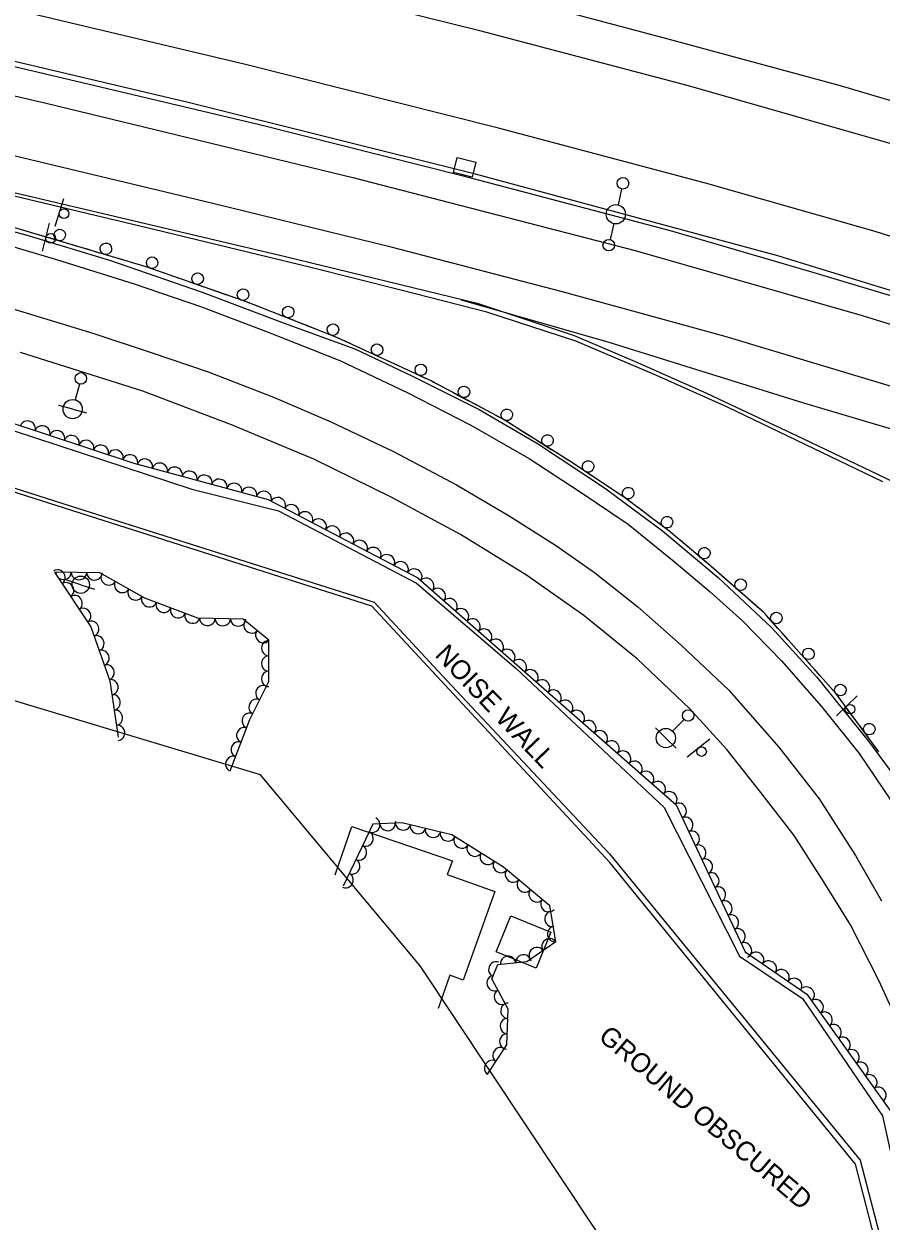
# Model space of a CAD drawing. Extents: x 1722896 to 1754269, y 648279 to 666297.
# Drawn here: x 1729933.1 to 1730155.7, y 652271.6 to 652582.6 of the extents above; entities that cross this region are included whole.
import ezdxf

# ---------------------------------------------------------------- set-up
doc = ezdxf.new("R2010")
doc.units = 0
for name, color, linetype in [('DESIGN - CENTERLINE - Proposed Text', 7, 'Continuous'), ('DESIGN - PUBLIC HEARING - Shapes', 7, 'Continuous'), ('DESIGN - SCRATCH - User 1', 7, 'Continuous'), ('SURVEY - CENTERLINE - Preliminary', 7, 'Continuous'), ('SURVEY - CENTERLINE - Preliminary Text', 7, 'Continuous'), ('SURVEY - DRAINAGE - Natural Features', 7, 'Continuous'), ('SURVEY - DTM - Breaklines', 7, 'Continuous'), ('SURVEY - VEGETATION - Features with Text', 7, 'Continuous')]:
    doc.layers.add(name, color=color, linetype=linetype)

msp = doc.modelspace()

# ---------------------------------------------------------------- linework, layer by layer
at = {"layer": 'DESIGN - CENTERLINE - Proposed Text'}
msp.add_lwpolyline([(1730013.96, 652361.53), (1730018.28, 652374.1), (1730044.37, 652365.21), (1730043.02, 652361.67), (1730055.41, 652357.27), (1730047.19, 652334.16), (1730043.67, 652335.5), (1730040.65, 652326.82)], dxfattribs=at)
msp.add_lwpolyline([(1730059.51, 652350.89), (1730069.89, 652346.65), (1730066.09, 652337.35), (1730055.71, 652341.59)], close=True, dxfattribs=at)
at = {"layer": 'DESIGN - PUBLIC HEARING - Shapes'}
for p, q in [((1729941.21, 652530.08), (1729943.48, 652537.22)), ((1729937.92, 652523.53), (1729939.79, 652530.79)), ((1730144.07, 652402.83), (1730149.42, 652408.08)), ((1730105.36, 652392.17), (1730111.19, 652396.88))]:
    msp.add_line(p, q, dxfattribs=at)
for centre in [(1729943.52, 652533.3), (1729940.05, 652526.88), (1730147.62, 652404.59), (1730109.06, 652393.58)]:
    msp.add_circle(centre, 1.25, dxfattribs=at)
at = {"layer": 'DESIGN - SCRATCH - User 1'}
for points in [[(1730260.5, 652481.12), (1730200.23, 652500.38), (1730128.84, 652522.38), (1730050.34, 652543.58), (1729975.77, 652562.21), (1729903.48, 652579.22), (1729810.16, 652600.96), (1729713.26, 652623.18), (1729589.34, 652652.13), (1729504.2, 652671.83), (1729418.48, 652691.69), (1729323.79, 652714.91), (1729300.24, 652718.9), (1729241.89, 652732.44), (1729159, 652752.12), (1729085.49, 652769.36), (1729012.25, 652788.71), (1728967.13, 652802.09)], [(1729322.32, 652714.08), (1729353.29, 652706.05), (1729426.46, 652688.63), (1729487, 652674.52), (1729543.44, 652661.54), (1729603.31, 652647.77), (1729684.6, 652628.54), (1729746.94, 652614.26), (1729794.94, 652603.07), (1729852.02, 652590.16), (1729894.66, 652579.99), (1729944.99, 652568.14), (1729994.29, 652556.46), (1730046.83, 652543.24), (1730100.94, 652528.96), (1730138.19, 652518.06), (1730180.91, 652505.22), (1730226.29, 652490.48), (1730260.14, 652479.46), (1730260.49, 652479.32)], [(1730155.11, 652393.52), (1730144.08, 652408.45), (1730135.73, 652417.94), (1730125.19, 652429.69), (1730110.77, 652442.32), (1730100.58, 652450.92), (1730089.44, 652459.3), (1730075.54, 652468.54), (1730057.34, 652480.01), (1730038.85, 652489.84), (1730014.4, 652501.15), (1729990.88, 652510.38), (1729964.82, 652519.52), (1729928.18, 652530.42), (1729886.57, 652541.81), (1729844.85, 652552.44), (1729803.55, 652565.53), (1729787.6, 652570.85)], [(1730156.12, 652463.67), (1730115.8, 652483.07), (1730097.15, 652491.31), (1730076.44, 652500.16), (1730053.34, 652507.68), (1730031.02, 652513.43), (1730007.63, 652519.31), (1729966.83, 652529.17), (1729878.66, 652550.21), (1729811, 652566.11), (1729790.9, 652570.56), (1729791.32, 652572.2), (1729835.78, 652561.08), (1729891.23, 652548.04), (1729941.54, 652536.16), (1730001.06, 652522.18), (1730050.79, 652510.07), (1730075.99, 652501.68), (1730092.46, 652494.61), (1730110.48, 652486.56), (1730135.33, 652474.9), (1730169.02, 652458.81)], [(1729710.95, 652524.89), (1729776.44, 652507.44), (1729862.1, 652483.88), (1729945.16, 652457.43), (1730024.08, 652432.36), (1730042.84, 652412.15), (1730085.15, 652367.01), (1730150.27, 652287.4), (1730165.53, 652228.54), (1730168.51, 652212.11), (1730166.64, 652211.96), (1730163.75, 652229.34), (1730149.01, 652286.42), (1730085.22, 652364.8), (1730023.49, 652431.35), (1729919.69, 652464.42), (1729854.38, 652484.95), (1729763.84, 652509.44), (1729638.78, 652542.79)], [(1729935.97, 652528.1), (1729933.71, 652528.77)], [(1729938.22, 652527.43), (1729935.97, 652528.1)], [(1729944.16, 652525.66), (1729939.75, 652526.98)], [(1729947.95, 652524.54), (1729945.7, 652525.21)], [(1729950.2, 652523.87), (1729947.95, 652524.54)], [(1729956.14, 652522.1), (1729951.73, 652523.41)], [(1729959.93, 652520.97), (1729957.68, 652521.65)], [(1729962.18, 652520.31), (1729959.93, 652520.97)], [(1729968.07, 652518.38), (1729964.82, 652519.52), (1729963.72, 652519.85)], [(1729971.8, 652517.07), (1729969.58, 652517.85)], [(1729974.02, 652516.29), (1729971.8, 652517.07)], [(1729979.87, 652514.24), (1729975.53, 652515.76)], [(1729983.6, 652512.93), (1729981.38, 652513.71)], [(1729985.81, 652512.16), (1729983.6, 652512.93)], [(1729991.65, 652510.08), (1729990.88, 652510.38), (1729987.32, 652511.63)], [(1729995.33, 652508.63), (1729993.14, 652509.49)], [(1729997.52, 652507.77), (1729995.33, 652508.63)], [(1730003.29, 652505.51), (1729999.01, 652507.19)], [(1730006.97, 652504.07), (1730004.78, 652504.92)], [(1730009.15, 652503.21), (1730006.97, 652504.07)], [(1730014.91, 652500.91), (1730014.4, 652501.15), (1730010.64, 652502.62)], [(1730018.5, 652499.25), (1730016.36, 652500.24)], [(1730020.63, 652498.27), (1730018.5, 652499.25)], [(1730026.26, 652495.66), (1730022.08, 652497.59)], [(1730029.84, 652494.01), (1730027.71, 652494.99)], [(1730031.98, 652493.02), (1730029.84, 652494.01)], [(1730037.6, 652490.42), (1730033.43, 652492.35)], [(1730041.12, 652488.63), (1730039.05, 652489.73)], [(1730043.2, 652487.53), (1730041.12, 652488.63)], [(1730048.67, 652484.62), (1730044.61, 652486.78)], [(1730052.16, 652482.76), (1730050.09, 652483.86)], [(1730054.24, 652481.66), (1730052.16, 652482.76)], [(1730059.61, 652478.58), (1730057.34, 652480.01), (1730055.65, 652480.91)], [(1730062.95, 652476.47), (1730060.96, 652477.72)], [(1730064.94, 652475.22), (1730062.95, 652476.47)], [(1730070.19, 652471.91), (1730066.29, 652474.36)], [(1730073.53, 652469.81), (1730071.54, 652471.06)], [(1730075.52, 652468.55), (1730073.53, 652469.81)], [(1730080.68, 652465.12), (1730076.85, 652467.67)], [(1730083.97, 652462.93), (1730082.01, 652464.23)], [(1730085.93, 652461.63), (1730083.97, 652462.93)], [(1730091.02, 652458.1), (1730089.44, 652459.3), (1730087.26, 652460.75)], [(1730094.18, 652455.73), (1730092.3, 652457.14)], [(1730096.06, 652454.32), (1730094.18, 652455.73)], [(1730100.99, 652450.57), (1730100.58, 652450.92), (1730097.33, 652453.36)], [(1730104.01, 652448.02), (1730102.21, 652449.54)], [(1730105.81, 652446.5), (1730104.01, 652448.02)], [(1730110.54, 652442.51), (1730107.03, 652445.47)], [(1730113.52, 652439.91), (1730111.75, 652441.45)], [(1730115.29, 652438.36), (1730113.52, 652439.91)], [(1730119.96, 652434.28), (1730116.49, 652437.31)], [(1730122.93, 652431.68), (1730121.16, 652433.22)], [(1730124.7, 652430.13), (1730122.93, 652431.68)], [(1730128.89, 652425.57), (1730125.82, 652428.99)], [(1730131.53, 652422.63), (1730129.96, 652424.38)], [(1730133.09, 652420.88), (1730131.53, 652422.63)], [(1730137.22, 652416.24), (1730135.73, 652417.94), (1730134.16, 652419.68)], [(1730139.82, 652413.28), (1730138.27, 652415.04)], [(1730141.38, 652411.52), (1730139.82, 652413.28)], [(1730145.33, 652406.75), (1730144.08, 652408.45), (1730142.43, 652410.31)], [(1730147.68, 652403.57), (1730146.29, 652405.46)], [(1730149.08, 652401.68), (1730147.68, 652403.57)], [(1730152.77, 652396.7), (1730150.03, 652400.4)], [(1730155.11, 652393.52), (1730153.72, 652395.41)]]:
    msp.add_lwpolyline(points, dxfattribs=at)
for centre, start, end in [((1729942.41, 652527.75), 6.6967, 6.6869), ((1729954.39, 652524.19), 6.6967, 6.6869), ((1729966.42, 652520.55), 3.9321, 3.9223), ((1729978.22, 652516.41), 3.9321, 3.9223), ((1729990.01, 652512.27), 3.9321, 3.9223), ((1730001.72, 652507.74), 1.829, 1.8192), ((1730013.35, 652503.17), 1.829, 1.8192), ((1730024.82, 652497.98), 358.4422, 358.4324), ((1730036.16, 652492.73), 358.4422, 358.4324), ((1730047.37, 652487.01), 355.2567, 355.2468), ((1730058.48, 652481.06), 351.0441, 351.0343), ((1730069.06, 652474.4), 351.0441, 351.0343), ((1730079.61, 652467.63), 349.6354, 349.6256), ((1730090.02, 652460.71), 349.6354, 349.6256), ((1730100.09, 652453.16), 346.307, 346.2972), ((1730109.77, 652445.12), 343.0958, 343.086), ((1730119.23, 652436.91), 342.0779, 342.0681), ((1730128.49, 652428.27), 335.1128, 335.103), ((1730136.83, 652418.95), 335.1128, 335.103), ((1730145.09, 652409.56), 334.6142, 334.6044), ((1730152.62, 652399.42), 329.7361, 329.7263)]:
    msp.add_arc(centre, 1.5, start, end, dxfattribs=at)
at = {"layer": 'SURVEY - CENTERLINE - Preliminary'}
for points in [[(1729712.09, 652539.06), (1729728.16, 652532.32), (1729731.95, 652531.44), (1729747.26, 652527.61), (1729783.86, 652517.45), (1729852.77, 652501.75), (1729907.09, 652484.58), (1729976.73, 652461.75), (1729999.25, 652456.08), (1730035.09, 652437.32), (1730060.96, 652415.12), (1730099.34, 652379.07), (1730118.88, 652340.44), (1730135.26, 652329.44), (1730156.05, 652298.94), (1730163.28, 652265.89), (1730169.18, 652222.37), (1730169.88, 652205.25), (1730158.68, 652204.09), (1730146.64, 652237.53), (1730139.98, 652255.94), (1730101.32, 652254.25), (1730090.54, 652255.85)], [(1730090.54, 652255.85), (1730036, 652337.91), (1729994.57, 652387.51), (1729869.07, 652425.27), (1729760.53, 652456.24), (1729772.95, 652462.64), (1729809.33, 652453.29), (1729823.84, 652469.84), (1729849.89, 652467.63), (1729857.75, 652476.95), (1729812.74, 652489.8), (1729795.66, 652480.5), (1729760.73, 652486.71), (1729733.92, 652471.18), (1729724.15, 652467.9), (1729664.75, 652484.03)]]:
    msp.add_lwpolyline(points, dxfattribs=at)
at = {"layer": 'SURVEY - CENTERLINE - Preliminary Text'}
for points in [[(1730270.3, 652515.2), (1730228.96, 652529.12), (1730166.13, 652549.21), (1730105.7, 652566.49), (1730051.45, 652580.8), (1730001.69, 652593.2), (1729955.68, 652604.21), (1729906, 652615.94), (1729848.69, 652629.12), (1729783.93, 652644.03), (1729726.92, 652657.34), (1729658.34, 652673.01), (1729604.33, 652685.78), (1729534.44, 652701.71), (1729459.5, 652718.9), (1729384.48, 652736.76), (1729323.16, 652750.51), (1729258.16, 652765.72), (1729169.76, 652786), (1729121.61, 652797.37), (1729018.16, 652823.93), (1728918.71, 652854.37)], [(1730264.12, 652492.62), (1730202.7, 652513.21), (1730154.17, 652528.69), (1730110.08, 652541.21), (1730056.32, 652555.48), (1729990.67, 652572.07), (1729928.6, 652586.81), (1729860.63, 652602.43), (1729797.44, 652617.47), (1729715.52, 652636.12), (1729640.3, 652653.56), (1729569.25, 652670.14), (1729500.79, 652685.57), (1729431.64, 652701.97), (1729354.64, 652719.58), (1729285.63, 652735.52), (1729212.27, 652752.8), (1729127.4, 652772.45), (1729037.59, 652794.76), (1728950.93, 652819.74), (1728930.15, 652826.14)], [(1728923.18, 652804.43), (1728976.92, 652786.42), (1729028.71, 652771.38), (1729089.83, 652756), (1729155.11, 652740.87), (1729217.1, 652726.75), (1729283.33, 652711.33), (1729334.81, 652699.48), (1729422.85, 652679.58), (1729666.73, 652624.57), (1729724.92, 652611.43), (1729788.41, 652596.68), (1729859.59, 652580.32), (1729938.86, 652561.99), (1730018.53, 652542.72), (1730091.86, 652523.7), (1730150.75, 652506.89), (1730199.99, 652491.57), (1730225.61, 652483.06), (1730258.51, 652471.91)], [(1729313.44, 652763.39), (1729359.16, 652752.98), (1729405.2, 652742.92), (1729445.49, 652732.9), (1729483.13, 652724.56), (1729529.93, 652713.81), (1729584.3, 652701.06), (1729638.29, 652688.6), (1729679.44, 652678.98), (1729738.84, 652665.33), (1729794.39, 652652.3), (1729839.68, 652641.7), (1729884.25, 652631.88), (1729931.01, 652620.85), (1729974.63, 652610.32), (1730017.13, 652600.05), (1730062.15, 652588.94), (1730099.35, 652579), (1730145.03, 652566.56), (1730174.24, 652557.91), (1730207.51, 652547.77), (1730238.01, 652536.75), (1730272.76, 652524.88)], [(1730254.53, 652456.82), (1730250.06, 652458.51), (1730204.24, 652474.26), (1730164.72, 652486.48), (1730115.23, 652501.41), (1730072.65, 652513.09), (1730028.51, 652524.57), (1729982.18, 652535.95), (1729930.49, 652548.32), (1729876.45, 652560.54), (1729824.27, 652572.87), (1729762.63, 652586.89), (1729723.44, 652596.01)], [(1729719.86, 652579.69), (1729751.72, 652571.47), (1729784.3, 652563.22), (1729813.6, 652555.7), (1729841.56, 652548.32), (1729881.54, 652537.96), (1729920.24, 652527.74), (1729941.62, 652521.43), (1729961.73, 652515.05), (1729979.23, 652509.1), (1729996.52, 652502.56), (1730015.18, 652495.12), (1730032.84, 652486.79), (1730049.02, 652478.46), (1730064.28, 652469.66), (1730077.57, 652461.05), (1730090, 652452.61), (1730101.97, 652442.99), (1730111.3, 652435.11), (1730119.8, 652427.47), (1730129.82, 652417.18), (1730140.2, 652405.31), (1730149.97, 652393.07), (1730158.31, 652380.8)], [(1729790.8, 652572.08), (1729745.5, 652582.35), (1729744.78, 652578.02), (1729774.09, 652570.27), (1729806.92, 652561.19), (1729849.03, 652550.26), (1729901.03, 652536.52), (1729933.66, 652527.76), (1729955.3, 652521.19), (1729979.44, 652512.95), (1730000.65, 652504.83), (1730019.07, 652498.16), (1730034.01, 652491.12), (1730051.28, 652482.46), (1730066.45, 652473.59), (1730083.89, 652462.04), (1730098.93, 652450.95), (1730113.36, 652438.8), (1730127.25, 652425.77), (1730138.99, 652412.87), (1730152.63, 652395.91), (1730159.01, 652387.36)], [(1729663.92, 652578.37), (1729721.29, 652563.73), (1729773.42, 652550.21), (1729822.73, 652537.33), (1729880.29, 652522.14), (1729903.71, 652516.01), (1729930.83, 652508.44), (1729951.3, 652502.14), (1729966.17, 652497.23), (1729980.97, 652492.21), (1729997.88, 652485.6), (1730012.67, 652479.35), (1730029.07, 652471.55), (1730045.47, 652462.87), (1730059.15, 652454.78), (1730071.4, 652447.05), (1730081.28, 652440.12), (1730092.53, 652431.14), (1730103.75, 652421.21), (1730116.11, 652409.51), (1730129.11, 652394.72), (1730139.57, 652381.29), (1730149.03, 652366.61), (1730155.81, 652354.76)], [(1730251.24, 652447.34), (1730215, 652459.46), (1730178.82, 652471.25), (1730135.6, 652484.11), (1730085.03, 652499.86), (1730046.74, 652510.81)], [(1730162.43, 652318.02), (1730155.2, 652333.94), (1730147.74, 652348.57), (1730140.87, 652359.55), (1730133.1, 652371.81), (1730124.49, 652382.96), (1730115.58, 652394.07), (1730105.96, 652404.79), (1730092.36, 652417.65), (1730078.49, 652428.93), (1730063.62, 652439.37), (1730046.5, 652449.97), (1730028.67, 652459.6), (1730008.37, 652469.5), (1729986.98, 652478.49), (1729964, 652487.19), (1729932.27, 652497.22)]]:
    msp.add_lwpolyline(points, dxfattribs=at)
at = {"layer": 'SURVEY - DRAINAGE - Natural Features'}
msp.add_line((1730047.55, 652545.32), (1730047.55, 652545.32), dxfattribs=at)
msp.add_lwpolyline([(1730044.64, 652543.99), (1730045.62, 652547.87), (1730050.47, 652546.64), (1730049.48, 652542.76), (1730044.64, 652543.99)], dxfattribs=at)
at = {"layer": 'SURVEY - DTM - Breaklines'}
for p, q in [((1730088.31, 652539.73), (1730087.37, 652535.59)), ((1730086.25, 652530.71), (1730085.3, 652526.57)), ((1729947.53, 652489.05), (1729946.43, 652484.94)), ((1729945.78, 652482.53), (1729942.16, 652483.5)), ((1729945.78, 652482.53), (1729949.41, 652481.56)), ((1729947.87, 652436.92), (1729944.3, 652438.07)), ((1729947.87, 652436.92), (1729951.44, 652435.76)), ((1730099.78, 652397.08), (1730097.11, 652399.73)), ((1730104.53, 652401.87), (1730101.54, 652398.86)), ((1730099.78, 652397.08), (1730102.44, 652394.44))]:
    msp.add_line(p, q, dxfattribs=at)
for centre, radius in [((1730088.65, 652541.19), 1.5), ((1730086.81, 652533.15), 2.5), ((1730084.97, 652525.11), 1.5), ((1729947.91, 652490.5), 1.5), ((1729945.78, 652482.53), 2.5), ((1729947.87, 652436.92), 2.25), ((1730105.59, 652402.94), 1.5), ((1730099.78, 652397.08), 2.5)]:
    msp.add_circle(centre, radius, dxfattribs=at)
at = {"layer": 'SURVEY - VEGETATION - Features with Text'}
for points in [[(1729714.11, 652540.99), (1729737.14, 652533.33), (1729764.39, 652524.93), (1729818.06, 652511.42), (1729854.61, 652503.23), (1729904.79, 652487.26), (1729961.66, 652468.47), (1729996.53, 652459.02), (1730035.41, 652438.67), (1730102.51, 652379.73), (1730120.4, 652341.52), (1730136.4, 652330.56), (1730158.18, 652300.06), (1730169.43, 652249.19), (1730170.91, 652201.84), (1730165.15, 652167.2), (1730168.44, 652157.78), (1730155.04, 652104.77), (1730135.05, 652092.16), (1730123.31, 652106.61), (1730092.69, 652120.33)], [(1729986.66, 652388.53), (1729991.79, 652401.92), (1729996.68, 652411.75), (1729996.73, 652422.47), (1729990.03, 652428.01), (1729978.28, 652428.23), (1729964.52, 652433.45), (1729952.8, 652440), (1729941.04, 652440.18), (1729950.52, 652425.99), (1729955.44, 652411.98), (1729957.59, 652397.33)], [(1730053.52, 652309.74), (1730058.49, 652317.36), (1730058.81, 652326.65), (1730054.63, 652334.51), (1730056.19, 652338.26), (1730063.73, 652339.03), (1730071.24, 652344.28), (1730069.66, 652353.49), (1730057.61, 652363.56), (1730044.26, 652371.93), (1730031.22, 652375.1), (1730023.72, 652374.68), (1730015.99, 652358.57)]]:
    msp.add_lwpolyline(points, dxfattribs=at)
for centre, major_axis in [((1729934.12, 652477.57), (1.9, -0.63)), ((1729937.92, 652476.32), (1.9, -0.63)), ((1729941.72, 652475.06), (1.9, -0.63)), ((1729945.52, 652473.81), (1.9, -0.63)), ((1729949.31, 652472.55), (1.9, -0.63)), ((1729953.11, 652471.3), (1.9, -0.63)), ((1729956.91, 652470.04), (1.9, -0.63)), ((1729960.71, 652468.79), (1.9, -0.63)), ((1729964.55, 652467.69), (1.93, -0.52)), ((1729968.41, 652466.64), (1.93, -0.52)), ((1729972.27, 652465.6), (1.93, -0.52)), ((1729976.14, 652464.55), (1.93, -0.52)), ((1729980, 652463.51), (1.93, -0.52)), ((1729983.86, 652462.46), (1.93, -0.52)), ((1729987.72, 652461.41), (1.93, -0.52)), ((1729991.58, 652460.37), (1.93, -0.52)), ((1729995.44, 652459.32), (1.93, -0.52)), ((1729999.07, 652457.69), (1.77, -0.93)), ((1730002.62, 652455.84), (1.77, -0.93)), ((1730006.16, 652453.98), (1.77, -0.93)), ((1730009.7, 652452.13), (1.77, -0.93)), ((1730013.25, 652450.27), (1.77, -0.93)), ((1730016.79, 652448.42), (1.77, -0.93)), ((1730020.33, 652446.56), (1.77, -0.93)), ((1730023.88, 652444.71), (1.77, -0.93)), ((1730027.42, 652442.85), (1.77, -0.93)), ((1730030.97, 652441), (1.77, -0.93)), ((1729941.94, 652438.84), (1.11, -1.66)), ((1729943.42, 652440.14), (-2, 0.03)), ((1729947.42, 652440.08), (-2, 0.03)), ((1729951.42, 652440.02), (-2, 0.03)), ((1730034.51, 652439.14), (1.77, -0.93)), ((1729944.16, 652435.51), (1.11, -1.66)), ((1729955.09, 652438.72), (-1.75, 0.98)), ((1729958.58, 652436.77), (-1.75, 0.98)), ((1730037.65, 652436.7), (1.5, -1.32)), ((1729946.38, 652432.18), (1.11, -1.66)), ((1729962.07, 652434.82), (-1.75, 0.98)), ((1729965.64, 652433.03), (-1.87, 0.71)), ((1730040.66, 652434.06), (1.5, -1.32)), ((1730043.66, 652431.42), (1.5, -1.32)), ((1729948.6, 652428.86), (1.11, -1.66)), ((1729969.38, 652431.61), (-1.87, 0.71)), ((1729973.12, 652430.19), (-1.87, 0.71)), ((1730046.67, 652428.78), (1.5, -1.32)), ((1729950.7, 652425.47), (0.66, -1.89)), ((1729976.86, 652428.77), (-1.87, 0.71)), ((1729980.76, 652428.19), (-2, 0.04)), ((1729984.76, 652428.11), (-2, 0.04)), ((1729988.76, 652428.03), (-2, 0.04)), ((1729992.13, 652426.28), (-1.54, 1.27)), ((1730049.67, 652426.14), (1.5, -1.32)), ((1729995.21, 652423.73), (-1.54, 1.27)), ((1730052.68, 652423.5), (1.5, -1.32)), ((1729952.03, 652421.7), (0.66, -1.89)), ((1729996.72, 652420.44), (0.01, 2)), ((1730055.68, 652420.86), (1.5, -1.32)), ((1729953.36, 652417.92), (0.66, -1.89)), ((1729996.7, 652416.44), (0.01, 2)), ((1730058.69, 652418.22), (1.5, -1.32)), ((1729954.68, 652414.15), (0.66, -1.89)), ((1730061.69, 652415.58), (1.5, -1.32)), ((1730064.7, 652412.94), (1.5, -1.32)), ((1729955.69, 652410.3), (0.29, -1.98)), ((1729996.68, 652412.44), (0.01, 2)), ((1730067.7, 652410.3), (1.5, -1.32)), ((1729995.2, 652408.79), (0.89, 1.79)), ((1730070.71, 652407.66), (1.5, -1.32)), ((1729956.27, 652406.34), (0.29, -1.98)), ((1729993.42, 652405.2), (0.89, 1.79)), ((1730073.71, 652405.02), (1.5, -1.32)), ((1729956.85, 652402.38), (0.29, -1.98)), ((1729991.67, 652401.61), (0.72, 1.87)), ((1730076.72, 652402.38), (1.5, -1.32)), ((1729957.43, 652398.43), (0.29, -1.98)), ((1729990.24, 652397.87), (0.72, 1.87)), ((1730079.72, 652399.74), (1.5, -1.32)), ((1729988.81, 652394.14), (0.72, 1.87)), ((1730082.73, 652397.1), (1.5, -1.32)), ((1730085.73, 652394.46), (1.5, -1.32)), ((1730088.74, 652391.82), (1.5, -1.32)), ((1729987.38, 652390.4), (0.72, 1.87)), ((1730091.74, 652389.18), (1.5, -1.32)), ((1730094.75, 652386.54), (1.5, -1.32)), ((1730097.75, 652383.9), (1.5, -1.32)), ((1730100.76, 652381.26), (1.5, -1.32)), ((1730103.22, 652378.21), (0.85, -1.81)), ((1730023.65, 652374.53), (-0.86, -1.8)), ((1730027.55, 652374.9), (-2, -0.11)), ((1730031.53, 652375.03), (-1.94, 0.47)), ((1730035.42, 652374.08), (-1.94, 0.47)), ((1730104.91, 652374.59), (0.85, -1.81)), ((1730021.92, 652370.93), (-0.86, -1.8)), ((1730039.31, 652373.13), (-1.94, 0.47)), ((1730043.19, 652372.19), (-1.94, 0.47)), ((1730046.72, 652370.39), (-1.69, 1.06)), ((1730106.61, 652370.97), (0.85, -1.81)), ((1730020.19, 652367.32), (-0.86, -1.8)), ((1730050.11, 652368.26), (-1.69, 1.06)), ((1730108.31, 652367.34), (0.85, -1.81)), ((1730018.46, 652363.71), (-0.86, -1.8)), ((1730053.5, 652366.14), (-1.69, 1.06)), ((1730110, 652363.72), (0.85, -1.81)), ((1730056.89, 652364.02), (-1.69, 1.06)), ((1730060.02, 652361.54), (-1.53, 1.28)), ((1730111.7, 652360.1), (0.85, -1.81)), ((1730016.73, 652360.11), (-0.86, -1.8)), ((1730063.09, 652358.98), (-1.53, 1.28)), ((1730066.16, 652356.41), (-1.53, 1.28)), ((1730113.39, 652356.48), (0.85, -1.81)), ((1730069.23, 652353.85), (-1.53, 1.28)), ((1730115.09, 652352.85), (0.85, -1.81)), ((1730070.24, 652350.1), (-0.34, 1.97)), ((1730116.79, 652349.23), (0.85, -1.81)), ((1730070.92, 652346.16), (-0.34, 1.97)), ((1730118.48, 652345.61), (0.85, -1.81)), ((1730069.52, 652343.08), (1.64, 1.15)), ((1730120.18, 652341.99), (0.85, -1.81)), ((1730058.82, 652338.53), (1.99, 0.2)), ((1730062.8, 652338.93), (1.99, 0.2)), ((1730066.24, 652340.79), (1.64, 1.15)), ((1730123.27, 652339.55), (1.65, -1.13)), ((1730055.67, 652337.01), (0.77, 1.85)), ((1730126.57, 652337.29), (1.65, -1.13)), ((1730129.87, 652335.03), (1.65, -1.13)), ((1730055.24, 652333.37), (-0.94, 1.77)), ((1730133.17, 652332.77), (1.65, -1.13)), ((1730057.12, 652329.84), (-0.94, 1.77)), ((1730136.45, 652330.48), (1.16, -1.63)), ((1730058.8, 652326.26), (0.07, 2)), ((1730138.77, 652327.23), (1.16, -1.63)), ((1730141.1, 652323.97), (1.16, -1.63)), ((1730058.66, 652322.26), (0.07, 2)), ((1730143.42, 652320.72), (1.16, -1.63)), ((1730058.52, 652318.26), (0.07, 2)), ((1730145.75, 652317.46), (1.16, -1.63)), ((1730056.79, 652314.77), (1.09, 1.68)), ((1730148.07, 652314.21), (1.16, -1.63)), ((1730054.61, 652311.42), (1.09, 1.68)), ((1730150.4, 652310.95), (1.16, -1.63)), ((1730152.72, 652307.7), (1.16, -1.63)), ((1730155.05, 652304.44), (1.16, -1.63))]:
    msp.add_ellipse(centre, major_axis=major_axis, ratio=0.940188, start_param=0, end_param=3.141593, dxfattribs=at)

# ---------------------------------------------------------------- texts
at = {"layer": 'DESIGN - SCRATCH - User 1'}
msp.add_text('NOISE WALL', height=5, rotation=313.6189, dxfattribs=at).set_placement((1730039.61, 652418.49))
at = {"layer": 'SURVEY - CENTERLINE - Preliminary'}
msp.add_text('GROUND OBSCURED', height=5, rotation=319.8397, dxfattribs=at).set_placement((1730082.01, 652319))

doc.saveas('drawing.dxf')
